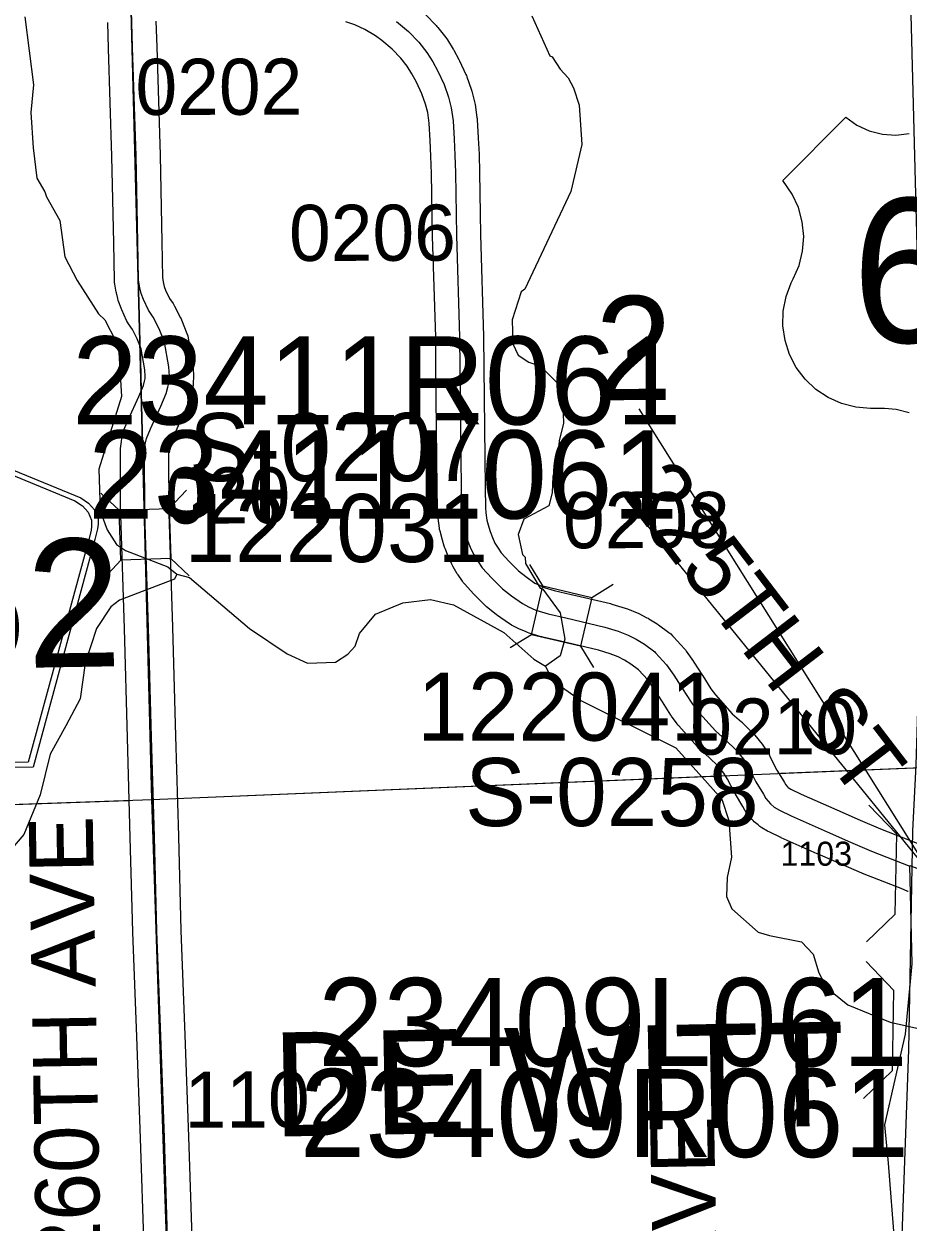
# Model space of a CAD drawing. Extents: x 128.7 to 185.5, y -21.4 to 12.6.
# Drawn here: x 150.052 to 151.156, y -8.747 to -7.251 of the extents above; entities that cross this region are included whole.
import ezdxf

# ---------------------------------------------------------------- set-up
doc = ezdxf.new("R2010")
doc.units = 0
for name, color, linetype in [('tdCoCorpBndry', 7, 'Continuous'), ('tdCoCorpTxt', 7, 'Continuous'), ('tdCoHydroRiver', 7, 'Continuous'), ('tdCoPriDiv', 7, 'Continuous'), ('tdCoSecRdNmbr', 7, 'Continuous'), ('tdCoSecRdTxt', 7, 'Continuous'), ('tdCoSecRteBand', 7, 'Continuous'), ('tdCoSecRteCL', 7, 'Continuous'), ('tdCoSectLine', 7, 'Continuous'), ('tdCoSectLinePart', 7, 'Continuous'), ('tdCoSectNmbr', 7, 'Continuous'), ('tdCoShieldCoRteHrd', 7, 'Continuous'), ('tdCoShieldUsRte', 7, 'Continuous'), ('tdCoStrucDivPri', 7, 'Continuous'), ('tdCoStrucPriMaintName', 7, 'Continuous'), ('tdCoStrucSec', 7, 'Continuous'), ('tdCoStrucSecCoName', 7, 'Continuous'), ('tdCoStrucSecFHWANum', 7, 'Continuous'), ('tdCoSurfAsphalt', 7, 'Continuous'), ('tdCoTwpBndryShd', 7, 'Continuous')]:
    doc.layers.add(name, color=color, linetype=linetype)

msp = doc.modelspace()

# ---------------------------------------------------------------- linework, layer by layer
at = {"layer": 'tdCoCorpBndry'}
msp.add_lwpolyline([(151.1472, -8.8755), (151.1314, -8.674), (151.1268, -8.6261), (151.1526, -8.5129), (151.1609, -8.4251), (151.158, -8.3022), (151.2204, -8.3263), (151.2238, -8.6694), (151.2318, -8.669), (151.7153, -8.645), (151.776, -8.642)], dxfattribs=at)
at = {"layer": 'tdCoHydroRiver'}
for points in [[(150.0533, -7.2424), (150.0641, -7.3273), (150.0606, -7.3621), (150.0637, -7.4062), (150.0681, -7.4439), (150.0782, -7.461), (150.08, -7.4672), (150.0968, -7.4966), (150.1031, -7.5422), (150.1183, -7.5716), (150.145, -7.6133), (150.1531, -7.6209), (150.1666, -7.6473), (150.1684, -7.652), (150.1701, -7.6551), (150.1737, -7.7165), (150.1453, -7.8074), (150.1471, -7.8595), (150.1558, -7.8829), (150.1675, -7.9014), (150.1788, -7.9089), (150.2315, -7.9292), (150.2429, -7.9383), (150.2588, -7.9425), (150.3336, -8.0062), (150.3805, -8.0377), (150.4061, -8.0495), (150.4408, -8.0483), (150.4562, -8.0383), (150.4654, -8.0285), (150.4711, -8.0125), (150.4908, -7.9882), (150.5251, -7.9744), (150.5596, -7.97), (150.5883, -7.9769), (150.651, -8.0111), (150.6885, -8.0445), (150.703, -8.0535)], [(150.6862, -7.2412), (150.7084, -7.291), (150.7116, -7.2925), (150.7216, -7.3079), (150.7315, -7.3186), (150.7382, -7.331), (150.7453, -7.3529), (150.7485, -7.4017), (150.7347, -7.4605), (150.6774, -7.5825), (150.6727, -7.5858), (150.6613, -7.6209), (150.6623, -7.6508), (150.6691, -7.6648), (150.6821, -7.6738), (150.6964, -7.6781), (150.7177, -7.6994), (150.7245, -7.715), (150.7257, -7.7497), (150.7202, -7.772), (150.7191, -7.7878), (150.7122, -7.8164), (150.7113, -7.837), (150.7072, -7.8529), (150.6762, -7.8697), (150.6689, -7.8889), (150.6745, -7.914), (150.6778, -7.917), (150.6781, -7.9249), (150.6965, -7.9559), (150.6997, -7.9573), (150.7212, -7.9866), (150.7271, -8.0195), (150.7215, -8.0402), (150.703, -8.0535), (150.7115, -8.0706), (150.7471, -8.0962), (150.8659, -8.1552), (150.9233, -8.2195), (150.9321, -8.2461), (150.9353, -8.2917), (150.9298, -8.3172), (150.9291, -8.3409), (150.9359, -8.3564), (150.9685, -8.3853), (150.9828, -8.3895), (151.0225, -8.3977), (151.0373, -8.4129), (151.0444, -8.4364), (151.0545, -8.455), (151.0805, -8.4762), (151.1333, -8.498), (151.2558, -8.5254)], [(150.2429, -7.9383), (150.24, -7.9447), (150.1714, -7.9707), (150.1606, -7.979), (150.1426, -8.0064), (150.1283, -8.0495), (150.122, -8.0939), (150.1042, -8.1277), (150.0849, -8.1631), (150.0724, -8.214), (150.052, -8.2636), (150.0353, -8.2831)]]:
    msp.add_lwpolyline(points, dxfattribs=at)
at = {"layer": 'tdCoPriDiv'}
msp.add_lwpolyline([(151.2829, -10.2902), (151.2686, -10.1968), (151.2623, -10.1448), (151.2454, -10.0415), (151.2238, -9.8826), (151.2125, -9.82), (151.2042, -9.7536), (151.1772, -9.5825), (151.1578, -9.4456), (151.158, -9.4466), (151.1447, -9.3629), (151.1369, -9.3035), (151.134, -9.2119), (151.1389, -9.1177), (151.1396, -9.0502), (151.1427, -8.926), (151.1567, -8.5322), (151.1616, -8.2589), (151.1658, -8.1769), (151.1753, -7.8635), (151.1738, -7.7314), (151.1675, -7.5445), (151.1566, -7.1267)], dxfattribs=at)
at = {"layer": 'tdCoSecRteBand'}
for points in [[(150.5537, -7.24), (150.5666, -7.2534), (150.5676, -7.2545), (150.5685, -7.2556), (150.5786, -7.2684), (150.5798, -7.2698), (150.5807, -7.2713), (150.5878, -7.2829), (150.5882, -7.2834), (150.5885, -7.284), (150.5949, -7.2956), (150.5954, -7.2965), (150.5959, -7.2974), (150.6038, -7.3143), (150.6045, -7.3157), (150.605, -7.3172), (150.6105, -7.3328), (150.6109, -7.3341), (150.6113, -7.3354), (150.6146, -7.3487), (150.615, -7.3502), (150.6152, -7.3518), (150.6175, -7.3682), (150.6177, -7.3694), (150.6177, -7.3706), (150.6191, -7.3935), (150.6191, -7.3937), (150.6191, -7.3938), (150.6201, -7.4138), (150.6201, -7.4142), (150.6201, -7.4146), (150.6206, -7.4366), (150.6206, -7.4367), (150.6206, -7.4367), (150.6215, -7.4881), (150.6221, -7.5147), (150.6259, -7.6411), (150.6259, -7.6414), (150.6259, -7.6417), (150.6263, -7.6803), (150.6278, -7.8304), (150.6283, -7.855), (150.6287, -7.8619), (150.6299, -7.871), (150.6323, -7.8798), (150.6339, -7.8853), (150.6368, -7.8927), (150.64, -7.8996), (150.6438, -7.9059), (150.6477, -7.9116), (150.6578, -7.9227), (150.6694, -7.9344), (150.6785, -7.9415), (150.6898, -7.9495), (150.6947, -7.9519), (150.7016, -7.955), (150.714, -7.9587), (150.7352, -7.9636), (150.7353, -7.9636), (150.7354, -7.9636), (150.7841, -7.9752), (150.7849, -7.9754), (150.7858, -7.9757), (150.8026, -7.9807), (150.804, -7.9811), (150.8053, -7.9817), (150.8176, -7.9868), (150.8187, -7.9872), (150.8197, -7.9877), (150.8298, -7.9928), (150.8311, -7.9934), (150.8323, -7.9941), (150.8424, -8.0005), (150.8434, -8.0011), (150.8442, -8.0017), (150.8572, -8.0112), (150.8597, -8.013), (150.8618, -8.0153), (150.8628, -8.0165), (150.8765, -8.0316), (150.8778, -8.0331), (150.8789, -8.0347), (150.8878, -8.0475), (150.888, -8.0478), (150.8882, -8.0481), (150.8993, -8.0651), (150.8994, -8.0653), (150.8996, -8.0655), (150.9097, -8.0815), (150.9152, -8.0891), (150.9363, -8.1127), (150.9478, -8.1228), (150.9485, -8.1234), (150.9491, -8.124), (150.9621, -8.1368), (150.9633, -8.138), (150.9644, -8.1394), (150.9735, -8.1506), (150.9744, -8.1518), (150.9752, -8.153), (150.9817, -8.163), (150.9826, -8.1644), (150.9833, -8.1659), (150.992, -8.183), (151.0009, -8.1977), (151.0012, -8.1982), (151.0014, -8.1986), (151.003, -8.2014), (151.0053, -8.2041), (151.0061, -8.2049), (151.0092, -8.2067), (151.0224, -8.213), (151.0667, -8.2329), (151.0959, -8.2456), (151.1213, -8.2565), (151.169, -8.2753)], [(150.2019, -8.7811), (150.1974, -8.6427), (150.193, -8.5163), (150.1881, -8.3853), (150.1881, -8.3852), (150.188, -8.385), (150.1848, -8.2674), (150.1811, -8.1427), (150.1811, -8.1427), (150.1811, -8.1426), (150.1774, -8.0063), (150.1728, -7.8646), (150.1727, -7.8642), (150.1727, -7.8637), (150.1725, -7.7848), (150.1725, -7.7831), (150.1727, -7.7813), (150.1737, -7.7727), (150.1738, -7.7713), (150.1741, -7.77), (150.1756, -7.7629), (150.1762, -7.76), (150.1773, -7.7574), (150.1822, -7.7456), (150.1824, -7.7451), (150.1826, -7.7447), (150.1953, -7.7166), (150.2012, -7.703), (150.2026, -7.6976), (150.2026, -7.6975), (150.2026, -7.6975), (150.2035, -7.6941), (150.2035, -7.6915), (150.203, -7.6832), (150.1984, -7.6571), (150.1934, -7.6444), (150.1875, -7.6329), (150.1827, -7.6258), (150.1813, -7.6238), (150.1802, -7.6215), (150.174, -7.6082), (150.1736, -7.6073), (150.1733, -7.6064), (150.1703, -7.5988), (150.1695, -7.5965), (150.169, -7.5942), (150.1675, -7.5873), (150.1674, -7.5867), (150.1673, -7.5862), (150.1656, -7.5763), (150.1652, -7.5741), (150.1651, -7.5718), (150.1641, -7.5247), (150.1641, -7.5247), (150.1641, -7.5247), (150.1619, -7.4168), (150.1577, -7.2818), (150.1567, -7.2495)], [(150.2167, -7.2479), (150.2177, -7.28), (150.2177, -7.28), (150.2177, -7.28), (150.2219, -7.4151), (150.2219, -7.4153), (150.2219, -7.4154), (150.2241, -7.5234), (150.225, -7.5682), (150.2263, -7.5753), (150.2271, -7.5793), (150.2289, -7.5838), (150.2336, -7.594), (150.2381, -7.6005), (150.2392, -7.6022), (150.2401, -7.6039), (150.2475, -7.6185), (150.2481, -7.6197), (150.2486, -7.621), (150.2553, -7.6378), (150.2564, -7.6406), (150.257, -7.6436), (150.2624, -7.6745), (150.2627, -7.6761), (150.2628, -7.6777), (150.2635, -7.6891), (150.2636, -7.6905), (150.2636, -7.692), (150.2633, -7.6994), (150.2632, -7.7027), (150.2624, -7.7059), (150.2606, -7.7126), (150.2587, -7.7202), (150.2581, -7.7224), (150.2572, -7.7246), (150.2503, -7.7406), (150.2502, -7.7408), (150.2501, -7.7411), (150.2374, -7.769), (150.2338, -7.7778), (150.2331, -7.7808), (150.2325, -7.7864), (150.2327, -7.8631), (150.2374, -8.0044), (150.2374, -8.0045), (150.2374, -8.0046), (150.2411, -8.1409), (150.2448, -8.2657), (150.2448, -8.2657), (150.2448, -8.2658), (150.248, -8.3832), (150.2529, -8.514), (150.2529, -8.5141), (150.253, -8.5141), (150.2574, -8.6406), (150.2574, -8.6407), (150.2574, -8.6407), (150.2618, -8.7793)], [(151.1558, -8.3345), (151.1556, -8.3345), (151.1471, -8.3311), (151.0989, -8.3121), (151.0984, -8.312), (151.098, -8.3118), (151.0722, -8.3007), (151.0721, -8.3007), (151.0721, -8.3006), (151.0426, -8.2878), (151.0425, -8.2877), (151.0423, -8.2877), (150.9975, -8.2676), (150.9971, -8.2674), (150.9968, -8.2673), (150.9822, -8.2603), (150.9812, -8.2598), (150.9801, -8.2592), (150.9733, -8.2552), (150.9706, -8.2537), (150.9684, -8.2516), (150.9638, -8.2475), (150.9623, -8.2461), (150.961, -8.2446), (150.9554, -8.2381), (150.9535, -8.2359), (150.9521, -8.2333), (150.9493, -8.2284), (150.9401, -8.2131), (150.9395, -8.2121), (150.939, -8.2111), (150.9305, -8.1944), (150.9257, -8.187), (150.9187, -8.1783), (150.9076, -8.1673), (150.8954, -8.1566), (150.8941, -8.1555), (150.8929, -8.1541), (150.8694, -8.128), (150.8684, -8.1268), (150.8674, -8.1255), (150.8605, -8.1158), (150.8599, -8.1151), (150.8595, -8.1143), (150.849, -8.0977), (150.8382, -8.0813), (150.8307, -8.0704), (150.8193, -8.0578), (150.8097, -8.0508), (150.8017, -8.0458), (150.7938, -8.0418), (150.7839, -8.0378), (150.7693, -8.0334), (150.7217, -8.022), (150.6996, -8.017), (150.6986, -8.0168), (150.6977, -8.0165), (150.6825, -8.0119), (150.6807, -8.0113), (150.679, -8.0106), (150.6697, -8.0065), (150.6689, -8.0061), (150.6681, -8.0058), (150.6607, -8.002), (150.6588, -8.001), (150.6571, -7.9998), (150.6433, -7.9901), (150.6427, -7.9897), (150.642, -7.9892), (150.6309, -7.9805), (150.6295, -7.9794), (150.6283, -7.9781), (150.6148, -7.9646), (150.6143, -7.9641), (150.6138, -7.9635), (150.6019, -7.9504), (150.6005, -7.9489), (150.5994, -7.9472), (150.5939, -7.9392), (150.5934, -7.9385), (150.593, -7.9378), (150.5878, -7.9293), (150.5868, -7.9277), (150.586, -7.9259), (150.5819, -7.9167), (150.5817, -7.9162), (150.5815, -7.9158), (150.5777, -7.9064), (150.577, -7.9049), (150.5766, -7.9033), (150.5745, -7.896), (150.5745, -7.8959), (150.5745, -7.8958), (150.5715, -7.8849), (150.5709, -7.8828), (150.5706, -7.8808), (150.569, -7.8686), (150.5689, -7.8675), (150.5688, -7.8664), (150.5684, -7.8578), (150.5683, -7.8573), (150.5683, -7.8567), (150.5679, -7.8314), (150.5678, -7.8312), (150.5678, -7.8311), (150.5663, -7.6809), (150.566, -7.6426), (150.5622, -7.5164), (150.5622, -7.5163), (150.5622, -7.5162), (150.5615, -7.4894), (150.5615, -7.4894), (150.5615, -7.4893), (150.5606, -7.4379), (150.5601, -7.4163), (150.5592, -7.3968), (150.5579, -7.3753), (150.556, -7.3617), (150.5534, -7.3513), (150.5489, -7.3385), (150.542, -7.3239), (150.5364, -7.3138), (150.5305, -7.3042), (150.5224, -7.294), (150.5116, -7.2827), (150.4988, -7.2719), (150.4909, -7.2663), (150.4776, -7.2583), (150.4652, -7.2525), (150.4539, -7.2485)]]:
    msp.add_lwpolyline(points, dxfattribs=at)
at = {"layer": 'tdCoSecRteCL'}
for points in [[(150.2318, -8.7803), (150.2274, -8.6417), (150.223, -8.5152), (150.218, -8.3842), (150.2148, -8.2666), (150.2111, -8.1418), (150.2074, -8.0054), (150.2027, -7.8636), (150.2025, -7.7847), (150.2035, -7.7761), (150.205, -7.7689), (150.2099, -7.7571), (150.2227, -7.7287), (150.2296, -7.7127), (150.2316, -7.7051), (150.2333, -7.6984), (150.2336, -7.691), (150.2328, -7.6797), (150.2274, -7.6488), (150.2207, -7.6321), (150.2134, -7.6175), (150.2074, -7.6089), (150.2013, -7.5956), (150.1983, -7.5879), (150.1968, -7.581), (150.1951, -7.5712), (150.1941, -7.524), (150.1919, -7.416), (150.1877, -7.2809), (150.1858, -7.2186)], [(150.5172, -7.2482), (150.5321, -7.2608), (150.545, -7.2742), (150.5551, -7.287), (150.5623, -7.2986), (150.5687, -7.3102), (150.5767, -7.3271), (150.5822, -7.3427), (150.5855, -7.356), (150.5878, -7.3724), (150.5891, -7.3952), (150.5901, -7.4152), (150.5906, -7.4373), (150.5915, -7.4887), (150.5921, -7.5155), (150.5959, -7.642), (150.5963, -7.6806), (150.5978, -7.8308), (150.5983, -7.8561), (150.5988, -7.8647), (150.6004, -7.8769), (150.6034, -7.8878), (150.6054, -7.8951), (150.6092, -7.9045), (150.6134, -7.9136), (150.6186, -7.9222), (150.6241, -7.9303), (150.636, -7.9434), (150.6495, -7.9569), (150.6606, -7.9656), (150.6743, -7.9752), (150.6818, -7.979), (150.6911, -7.9832), (150.7063, -7.9878), (150.7285, -7.9928), (150.7771, -8.0044), (150.7939, -8.0094), (150.8063, -8.0145), (150.8164, -8.0196), (150.8265, -8.0259), (150.8395, -8.0354), (150.8406, -8.0366), (150.8542, -8.0517), (150.8631, -8.0646), (150.8742, -8.0815), (150.8848, -8.0983), (150.8918, -8.108), (150.9152, -8.1341), (150.928, -8.1453), (150.941, -8.1582), (150.9501, -8.1694), (150.9566, -8.1794), (150.9657, -8.1976), (150.9752, -8.2133), (150.9782, -8.2187), (150.9838, -8.2251), (150.9884, -8.2293), (150.9952, -8.2332), (151.0098, -8.2402), (151.0546, -8.2603), (151.084, -8.2731), (151.1099, -8.2842), (151.158, -8.3032)]]:
    msp.add_lwpolyline(points, dxfattribs=at)
at = {"layer": 'tdCoSectLine'}
for points in [[(150.1854, -7.2186), (150.2118, -8.2199)], [(150.2118, -8.2199), (151.2135, -8.178)], [(149.2179, -8.2547), (150.2118, -8.2199)], [(150.2118, -8.2199), (150.245, -9.219)]]:
    msp.add_lwpolyline(points, dxfattribs=at)
at = {"layer": 'tdCoSectLinePart'}
for points in [[(150.1969, -7.6542), (150.1983, -7.7086)], [(150.9967, -8.1871), (151.2135, -8.178)], [(150.2418, -8.2186), (150.9292, -8.1899)], [(149.2479, -8.2537), (150.1819, -8.2209)]]:
    msp.add_lwpolyline(points, dxfattribs=at)
at = {"layer": 'tdCoShieldCoRteHrd'}
for points in [[(149.8239, -8.1837), (149.7371, -7.9023), (149.7329, -7.8892), (149.7321, -7.8833), (149.732, -7.8755), (149.736, -7.8651), (149.7432, -7.8565), (149.7526, -7.8497), (149.9186, -7.7744), (149.9261, -7.7726), (149.9365, -7.7715), (149.9469, -7.7723), (149.9545, -7.7738), (150.123, -7.8432), (150.1327, -7.8497), (150.1401, -7.8581), (150.1445, -7.8683), (150.1447, -7.8761), (150.144, -7.882), (150.1404, -7.8952), (150.0634, -8.1795)], [(149.8297, -8.1773), (149.7451, -7.9034), (149.7412, -7.8909), (149.7404, -7.8852), (149.7403, -7.8777), (149.7442, -7.8677), (149.751, -7.8595), (149.7601, -7.8529), (149.9194, -7.7807), (149.9266, -7.779), (149.9366, -7.7779), (149.9466, -7.7786), (149.9539, -7.7801), (150.1156, -7.8467), (150.125, -7.8529), (150.1321, -7.861), (150.1363, -7.8708), (150.1365, -7.8783), (150.1359, -7.884), (150.1324, -7.8967), (150.0574, -8.1733)]]:
    msp.add_lwpolyline(points, close=True, dxfattribs=at)
at = {"layer": 'tdCoShieldUsRte'}
msp.add_lwpolyline([(151.1571, -7.7368), (151.1408, -7.7326), (151.1261, -7.7314), (151.109, -7.7314), (151.0907, -7.7299), (151.0728, -7.7253), (151.056, -7.7178), (151.0407, -7.7076), (151.0273, -7.695), (151.0162, -7.6803), (151.0078, -7.664), (151.0021, -7.6465), (150.9995, -7.6283), (150.9999, -7.6099), (151.0034, -7.5918), (151.0099, -7.5746), (151.0123, -7.5698), (151.0196, -7.5529), (151.024, -7.5351), (151.0254, -7.5167), (151.0236, -7.4984), (151.0188, -7.4806), (151.0111, -7.4639), (150.9992, -7.4468), (151.0781, -7.3679), (151.0919, -7.3777), (151.1072, -7.3847), (151.1236, -7.3889), (151.1405, -7.39), (151.1573, -7.388)], dxfattribs=at)
at = {"layer": 'tdCoStrucDivPri'}
for points in [[(151.1037, -8.3976), (151.1397, -8.363), (151.1416, -8.263), (151.1069, -8.227)], [(151.1002, -8.593), (151.1362, -8.5583), (151.138, -8.4583), (151.1033, -8.4223)]]:
    msp.add_lwpolyline(points, dxfattribs=at)
at = {"layer": 'tdCoStrucPriMaintName'}
msp.add_lwpolyline([(150.8196, -7.7318), (151.1835, -8.312), (150.8056, -7.8469)], dxfattribs=at)
msp.add_lwpolyline([(150.8196, -7.7318), (151.1835, -8.312), (150.8056, -7.8469)], dxfattribs=at)
msp.add_lwpolyline([(150.8196, -7.7318), (151.1835, -8.312), (150.8056, -7.8469)], dxfattribs=at)
at = {"layer": 'tdCoStrucSec'}
for p, q in [((150.1709, -7.8584), (150.148, -7.8371)), ((150.2334, -7.8564), (150.2548, -7.8335)), ((150.1729, -7.921), (150.1516, -7.9439)), ((150.2355, -7.9189), (150.2584, -7.9403)), ((150.6999, -7.9531), (150.6834, -7.9265)), ((150.7609, -7.9674), (150.7875, -7.9509)), ((150.6856, -8.0141), (150.659, -8.0305)), ((150.7466, -8.0284), (150.7631, -8.055))]:
    msp.add_line(p, q, dxfattribs=at)
for points in [[(150.1729, -7.921), (150.1709, -7.8584), (150.2334, -7.8564), (150.2355, -7.9189)], [(150.7466, -8.0284), (150.6856, -8.0141), (150.6999, -7.9531), (150.7609, -7.9674)]]:
    msp.add_lwpolyline(points, close=True, dxfattribs=at)
at = {"layer": 'tdCoSurfAsphalt'}
for points in [[(150.2318, -8.7803), (150.2274, -8.6417), (150.223, -8.5152), (150.218, -8.3842), (150.2148, -8.2666), (150.2111, -8.1418), (150.2074, -8.0054), (150.2027, -7.8636), (150.2025, -7.7847), (150.2035, -7.7761), (150.205, -7.7689), (150.2099, -7.7571), (150.2227, -7.7287), (150.2296, -7.7127), (150.2316, -7.7051), (150.2333, -7.6984), (150.2336, -7.691), (150.2328, -7.6797), (150.2274, -7.6488), (150.2207, -7.6321), (150.2134, -7.6175), (150.2074, -7.6089), (150.2013, -7.5956), (150.1983, -7.5879), (150.1968, -7.581), (150.1951, -7.5712), (150.1941, -7.524), (150.1919, -7.416), (150.1877, -7.2809), (150.1858, -7.2186)], [(150.5172, -7.2482), (150.5321, -7.2608), (150.545, -7.2742), (150.5551, -7.287), (150.5623, -7.2986), (150.5687, -7.3102), (150.5767, -7.3271), (150.5822, -7.3427), (150.5855, -7.356), (150.5878, -7.3724), (150.5891, -7.3952), (150.5901, -7.4152), (150.5906, -7.4373), (150.5915, -7.4887), (150.5921, -7.5155), (150.5959, -7.642), (150.5963, -7.6806), (150.5978, -7.8308), (150.5983, -7.8561), (150.5988, -7.8647), (150.6004, -7.8769), (150.6034, -7.8878), (150.6054, -7.8951), (150.6092, -7.9045), (150.6134, -7.9136), (150.6186, -7.9222), (150.6241, -7.9303), (150.636, -7.9434), (150.6495, -7.9569), (150.6606, -7.9656), (150.6743, -7.9752), (150.6818, -7.979), (150.6911, -7.9832), (150.7063, -7.9878), (150.7285, -7.9928), (150.7771, -8.0044), (150.7939, -8.0094), (150.8063, -8.0145), (150.8164, -8.0196), (150.8265, -8.0259), (150.8395, -8.0354), (150.8406, -8.0366), (150.8542, -8.0517), (150.8631, -8.0646), (150.8742, -8.0815), (150.8848, -8.0983), (150.8918, -8.108), (150.9152, -8.1341), (150.928, -8.1453), (150.941, -8.1582), (150.9501, -8.1694), (150.9566, -8.1794), (150.9657, -8.1976), (150.9752, -8.2133), (150.9782, -8.2187), (150.9838, -8.2251), (150.9884, -8.2293), (150.9952, -8.2332), (151.0098, -8.2402), (151.0546, -8.2603), (151.084, -8.2731), (151.1099, -8.2842), (151.158, -8.3032)]]:
    msp.add_lwpolyline(points, dxfattribs=at)
at = {"layer": 'tdCoTwpBndryShd'}
msp.add_lwpolyline([(150.395, -13.7476), (150.378, -13.2238), (150.3466, -12.2212), (150.3134, -11.2212), (150.2794, -10.2174), (150.245, -9.219), (150.2118, -8.2199), (150.1854, -7.2186), (149.1912, -7.251), (148.1861, -7.2877), (147.1862, -7.3236), (146.1796, -7.3579), (145.1769, -7.3938), (144.1761, -7.4248), (143.1728, -7.4558), (142.1753, -7.4874), (141.1678, -7.5201), (140.1762, -7.5484), (139.1499, -7.567), (138.1783, -7.5984), (137.1762, -7.6276), (136.1739, -7.6508), (135.1725, -7.6763), (134.1612, -7.6994)], dxfattribs=at)

# ---------------------------------------------------------------- texts
at = {"layer": 'tdCoCorpTxt'}
msp.add_text('DE WITT', height=0.13, rotation=1.1161, dxfattribs=at).set_placement((150.3634, -8.6409))
at = {"layer": 'tdCoSecRdNmbr'}
for s, height, rotation, p in [('0202', 0.07, 0.1139, (150.1913, -7.365)), ('0206', 0.07, 0.1141, (150.383, -7.5473)), ('0204', 0.07, 0.1139, (150.2283, -7.8753)), ('0208', 0.07, 0.1143, (150.725, -7.9061)), ('0210', 0.07, 0.1144, (150.8838, -8.1638)), ('1103', 0.03, 0.1144, (150.9965, -8.3026)), ('1102', 0.07, 0.1139, (150.2525, -8.6296))]:
    msp.add_text(s, height=height, rotation=rotation, dxfattribs=at).set_placement(p)
at = {"layer": 'tdCoSecRdTxt'}
for s, rotation, p in [('225TH ST', 307.4617, (150.7969, -7.8369)), ('260TH AVE', 91, (150.1477, -8.8046)), ('267TH AVE', 91, (150.9234, -9.1797))]:
    msp.add_text(s, height=0.08, rotation=rotation, dxfattribs=at).set_placement(p)
at = {"layer": 'tdCoSectNmbr'}
msp.add_text('2', height=0.13, rotation=0.1142, dxfattribs=at).set_placement((150.765, -7.7212))
at = {"layer": 'tdCoShieldCoRteHrd'}
msp.add_text('Y62', height=0.16, rotation=1, dxfattribs=at).set_placement((149.7945, -8.0599))
at = {"layer": 'tdCoShieldUsRte'}
msp.add_text('61', height=0.18, dxfattribs=at).set_placement((151.0857, -7.6492))
at = {"layer": 'tdCoStrucPriMaintName'}
for s, p in [('23411R061', (150.1121, -7.7515)), ('23411R061', (150.1121, -7.7515)), ('23411R061', (150.1121, -7.7515)), ('23411L061', (150.1322, -7.869)), ('23411L061', (150.1322, -7.869)), ('23411L061', (150.1322, -7.869)), ('23409L061', (150.4191, -8.5527)), ('23409L061', (150.4191, -8.5527)), ('23409L061', (150.4191, -8.5527)), ('23409R061', (150.3963, -8.6663)), ('23409R061', (150.3963, -8.6663)), ('23409R061', (150.3963, -8.6663))]:
    msp.add_text(s, height=0.11, dxfattribs=at).set_placement(p)
at = {"layer": 'tdCoStrucSecCoName'}
for s, p in [('S-0207', (150.2584, -7.8222)), ('S-0258', (150.6027, -8.253))]:
    msp.add_text(s, height=0.085, dxfattribs=at).set_placement(p)
at = {"layer": 'tdCoStrucSecFHWANum'}
for s, p in [('122031', (150.2522, -7.9233)), ('122041', (150.5429, -8.1463))]:
    msp.add_text(s, height=0.085, dxfattribs=at).set_placement(p)

doc.saveas('drawing.dxf')
